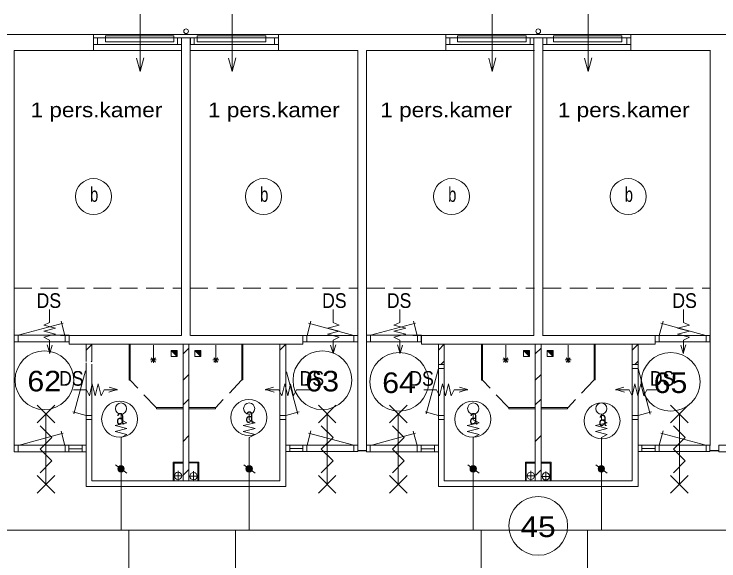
# Model space of a CAD drawing. Extents: x 295824 to 414724, y 24924 to 109024.
# Drawn here: x 308090 to 320090, y 38568 to 47876 of the extents above; entities that cross this region are included whole.
import ezdxf
from ezdxf.enums import TextEntityAlignment as Align

# ---------------------------------------------------------------- set-up
doc = ezdxf.new("R2010")
doc.units = 0
doc.header["$LTSCALE"] = 100
doc.linetypes.add('DOT_DASHED', pattern=[7.7, 5, -1.2, 0.3, -1.2])
doc.linetypes.add('MEDIUM_DASHED', pattern=[4.5, 3, -1.5])
for name, color, linetype, lineweight in [('1', 7, 'Continuous', 13), ('16', 7, 'Continuous', 13), ('24', 7, 'Continuous', 13), ('61', 7, 'Continuous', 13)]:
    doc.layers.add(name, color=color, linetype=linetype, lineweight=lineweight)

msp = doc.modelspace()

# ---------------------------------------------------------------- hatches: boundary and pattern name
at = {"layer": '24'}
for points in [[(309964.5, 40135, 1), (309855.9, 40135, 1)], [(312146.5, 40135, 1), (312037.9, 40135, 1)], [(315960.8, 40135, 1), (315852.2, 40135, 1)], [(318142.8, 40135, 1), (318034.2, 40135, 1)]]:
    msp.add_hatch(color=256, dxfattribs=at).paths.add_polyline_path(points)
at = {"layer": '61'}
for points in [[(310864.9, 42048.6), (310764.9, 42148.6), (310864.9, 42148.6)], [(311267.9, 42048.6), (311167.9, 42148.6), (311267.9, 42148.6)], [(316862.8, 42048.6), (316762.8, 42148.6), (316862.8, 42148.6)], [(317265.8, 42048.6), (317165.8, 42148.6), (317265.8, 42148.6)]]:
    msp.add_hatch(color=256, dxfattribs=at).paths.add_polyline_path(points)

# ---------------------------------------------------------------- linework, layer by layer
at = {"layer": '1'}
for p, q in [((309910.2, 40103.6), (309910.2, 39093.2)), ((312092.2, 40097), (312092.2, 39093.2)), ((315906.5, 40103.6), (315906.5, 39093.2)), ((318088.5, 40097), (318088.5, 39093.2)), ((310043.5, 38210.2), (310043.5, 39093.2)), ((311859, 38205.2), (311859, 39093.2)), ((316039.8, 38210.2), (316039.8, 39093.2)), ((317855.3, 38205.2), (317855.3, 39093.2))]:
    msp.add_line(p, q, dxfattribs=at)
at = {"layer": '16'}
for p, q in [((308594.4, 42478.5), (308794.4, 42528.5)), ((313624.7, 42478.5), (313424.7, 42528.5)), ((314557.3, 42478.5), (314757.3, 42528.5)), ((319587.6, 42478.5), (319387.6, 42528.5)), ((309470.8, 41380.3), (309420.8, 41580.3)), ((312748.2, 41380.3), (312798.2, 41580.3)), ((315433.7, 41380.3), (315383.7, 41580.3)), ((318711.2, 41380.3), (318761.2, 41580.3))]:
    msp.add_line(p, q, dxfattribs=at)
at = {"layer": '24'}
for p, q in [((310235, 46901.4), (310175.4, 47123.8)), ((311800.7, 46901.4), (311741.1, 47123.8)), ((316231.3, 46901.4), (316171.7, 47123.8)), ((317863.6, 46901.4), (317804, 47123.8)), ((308697.7, 42103.1), (308652.7, 42247.3)), ((313521.3, 42103.1), (313566.3, 42247.3)), ((314660.7, 42103.1), (314615.7, 42247.3)), ((319484.2, 42103.1), (319529.2, 42247.3)), ((308740.2, 42238.9), (308697.7, 42103.1)), ((313478.9, 42238.9), (313521.3, 42103.1)), ((314703.1, 42238.9), (314660.7, 42103.1)), ((319441.8, 42238.9), (319484.2, 42103.1)), ((309710.4, 41526.2), (309846.2, 41483.7)), ((312508.6, 41526.2), (312372.8, 41483.7)), ((315673.3, 41526.2), (315809.1, 41483.7)), ((318471.6, 41526.2), (318335.8, 41483.7)), ((309846.2, 41483.7), (309702, 41438.7)), ((312372.8, 41483.7), (312517, 41438.7)), ((315809.1, 41483.7), (315665, 41438.7)), ((318335.8, 41483.7), (318480, 41438.7)), ((309910.2, 40620.3), (309910.2, 40080.9)), ((312092.2, 40620.3), (312092.2, 40112)), ((315906.5, 40620.3), (315906.5, 40080.9)), ((318088.5, 40620.3), (318088.5, 40112)), ((309818.6, 40205.8), (310010.2, 40064.1)), ((312000.6, 40205.8), (312192.1, 40064.1)), ((315814.9, 40205.8), (316006.4, 40064.1)), ((317996.9, 40205.8), (318188.4, 40064.1)), ((304097.2, 39093.2), (328693.9, 39093.2))]:
    msp.add_line(p, q, dxfattribs=at)
for points in [[(310235, 47876.3), (310235, 46901.4), (310296.7, 47131.6)], [(311800.7, 47876.3), (311800.7, 46901.4), (311862.4, 47131.6)], [(316231.3, 47876.3), (316231.3, 46901.4), (316293, 47131.6)], [(317863.6, 47876.3), (317863.6, 46901.4), (317925.3, 47131.6)], [(308794.4, 42528.5), (308594.4, 42578.5), (308694.4, 42628.5), (308694.4, 42847.3)], [(313424.7, 42528.5), (313624.7, 42578.5), (313524.7, 42628.5), (313524.7, 42847.3)], [(314757.3, 42528.5), (314557.3, 42578.5), (314657.3, 42628.5), (314657.3, 42847.3)], [(319387.6, 42528.5), (319587.6, 42578.5), (319487.6, 42628.5), (319487.6, 42847.3)], [(308694.4, 42097.3), (308694.4, 42328.5), (308594.4, 42378.5), (308794.4, 42428.5), (308594.4, 42478.5)], [(313524.7, 42097.3), (313524.7, 42328.5), (313624.7, 42378.5), (313424.7, 42428.5), (313624.7, 42478.5)], [(314657.3, 42097.3), (314657.3, 42328.5), (314557.3, 42378.5), (314757.3, 42428.5), (314557.3, 42478.5)], [(319487.6, 42097.3), (319487.6, 42328.5), (319587.6, 42378.5), (319387.6, 42428.5), (319587.6, 42478.5)], [(309420.8, 41580.3), (309370.8, 41380.3), (309320.8, 41480.3), (309102, 41480.3)], [(309852, 41480.3), (309620.8, 41480.3), (309570.8, 41380.3), (309520.8, 41580.3), (309470.8, 41380.3)], [(312367, 41480.3), (312598.2, 41480.3), (312648.2, 41380.3), (312698.2, 41580.3), (312748.2, 41380.3)], [(312798.2, 41580.3), (312848.2, 41380.3), (312898.2, 41480.3), (313117, 41480.3)], [(315383.7, 41580.3), (315333.7, 41380.3), (315283.7, 41480.3), (315065, 41480.3)], [(315815, 41480.3), (315583.7, 41480.3), (315533.7, 41380.3), (315483.7, 41580.3), (315433.7, 41380.3)], [(318330, 41480.3), (318561.2, 41480.3), (318611.2, 41380.3), (318661.2, 41580.3), (318711.2, 41380.3)], [(318761.2, 41580.3), (318811.2, 41380.3), (318861.2, 41480.3), (319079.9, 41480.3)], [(309910.2, 41070.3), (309910.2, 40970.3), (310010.2, 40920.3), (309810.2, 40870.3), (310010.2, 40820.3), (309810.2, 40770.3), (310010.2, 40720.3), (309910.2, 40670.3), (309910.2, 40620.3)], [(312092.2, 41070.3), (312092.2, 40970.3), (312192.2, 40920.3), (311992.2, 40870.3), (312192.2, 40820.3), (311992.2, 40770.3), (312192.2, 40720.3), (312092.2, 40670.3), (312092.2, 40620.3)], [(315906.5, 41070.3), (315906.5, 40970.3), (316006.5, 40920.3), (315806.5, 40870.3), (316006.5, 40820.3), (315806.5, 40770.3), (316006.5, 40720.3), (315906.5, 40670.3), (315906.5, 40620.3)], [(318088.5, 41070.3), (318088.5, 40970.3), (318188.5, 40920.3), (317988.5, 40870.3), (318188.5, 40820.3), (317988.5, 40770.3), (318188.5, 40720.3), (318088.5, 40670.3), (318088.5, 40620.3)]]:
    msp.add_lwpolyline(points, dxfattribs=at)
for points in [[(309643.7, 47405.5), (310809.7, 47405.5), (310809.7, 47505.5), (309643.7, 47505.5)], [(311209.4, 47405.5), (312375.4, 47405.5), (312375.4, 47505.5), (311209.4, 47505.5)], [(315640, 47405.5), (316805.9, 47405.5), (316805.9, 47505.5), (315640, 47505.5)], [(317272.3, 47405.5), (318438.2, 47405.5), (318438.2, 47505.5), (317272.3, 47505.5)]]:
    msp.add_lwpolyline(points, close=True, dxfattribs=at)
for centre, radius in [((309910.2, 41162), 95), ((312092.2, 41162), 95), ((315906.5, 41162), 95), ((318088.5, 41162), 95), ((309910.2, 40135), 54.3), ((312092.2, 40135), 54.3), ((315906.5, 40135), 54.3), ((318088.5, 40135), 54.3)]:
    msp.add_circle(centre, radius, dxfattribs=at)
at = {"layer": '61'}
for p, q in [((301828.9, 47527.9), (333452, 47527.9)), ((309440.9, 47257.3), (309440.9, 47527.3)), ((312589.9, 47257.3), (312589.9, 47527.3)), ((313820.3, 47527.9), (333174.1, 47527.9)), ((315441, 47257.3), (315441, 47527.3)), ((318589.9, 47257.3), (318589.9, 47527.3)), ((309441.7, 47472.1), (310940.7, 47472.1)), ((309441.7, 47358.1), (309441.7, 47472.1)), ((309508.7, 47358.1), (309508.7, 47471.5)), ((310873.7, 47472.1), (312589.7, 47472.1)), ((310873.7, 47358.5), (310873.7, 47472.1)), ((310940.7, 47359.1), (310940.7, 47472.1)), ((310940.9, 47257.3), (310940.9, 47472.1)), ((311089.9, 47257.3), (311089.9, 47472.1)), ((311090.7, 47358.1), (311090.7, 47472.1)), ((311157.7, 47358.1), (311157.7, 47471.5)), ((312522.7, 47358.5), (312522.7, 47471.5)), ((312589.7, 47359.1), (312589.7, 47472.1)), ((315441.8, 47472.1), (316940.8, 47472.1)), ((315441.8, 47358.1), (315441.8, 47472.1)), ((315508.8, 47358.1), (315508.8, 47471.5)), ((316873.8, 47472.1), (318589.8, 47472.1)), ((316873.8, 47358.5), (316873.8, 47472.1)), ((316940.8, 47359.1), (316940.8, 47472.1)), ((316941, 47257.3), (316941, 47472.1)), ((317089.9, 47257.3), (317089.9, 47472.1)), ((317090.8, 47358.1), (317090.8, 47472.1)), ((317157.8, 47358.1), (317157.8, 47471.5)), ((318522.8, 47358.5), (318522.8, 47471.5)), ((318589.8, 47359.1), (318589.8, 47472.1)), ((309441.7, 47358.1), (310939.8, 47358.1)), ((311090.7, 47358.1), (312588.8, 47358.1)), ((315441.8, 47358.1), (316939.9, 47358.1)), ((317090.8, 47358.1), (318588.8, 47358.1)), ((308090.1, 40536.9), (308090.1, 47257.9)), ((313940.1, 40532.9), (313940.1, 47257.9)), ((314090.1, 40532.9), (314090.1, 47257.9)), ((314098.9, 47257.9), (316948.9, 47257.9)), ((319948.9, 47257.9), (317098.9, 47257.9)), ((319940.1, 40532.9), (319940.1, 47257.9)), ((308160.8, 42409.2), (308928.1, 42614.8)), ((308955.3, 42407.1), (308890.3, 42649.8)), ((313077.1, 42405.1), (313142.2, 42647.8)), ((313871.7, 42407.2), (313104.4, 42612.8)), ((314158.7, 42409.2), (314926, 42614.8)), ((314953.3, 42407.1), (314888.2, 42649.8)), ((319075.1, 42405.1), (319140.1, 42647.8)), ((319869.6, 42407.2), (319102.3, 42612.8)), ((308158.2, 42299.1), (308158.2, 42409.1)), ((310940.8, 42407.9), (308880.8, 42407.9)), ((308958.2, 42299.1), (308958.2, 42409.1)), ((309025.2, 42299.1), (309025.2, 42409.1)), ((311090.8, 42407.9), (313940.1, 42407.9)), ((311090.8, 42407.9), (313033.3, 42407.9)), ((313007.3, 42297.1), (313007.3, 42407.1)), ((313074.3, 42297.1), (313074.3, 42407.1)), ((313874.3, 42297.1), (313874.3, 42407.1)), ((313940.2, 42297.4), (313940.2, 42407.8)), ((314156.1, 42299.1), (314156.1, 42409.1)), ((316938.8, 42407.9), (314878.8, 42407.9)), ((314956.1, 42299.1), (314956.1, 42409.1)), ((315023.1, 42299.1), (315023.1, 42409.1)), ((317088.7, 42407.9), (319031.2, 42407.9)), ((317088.8, 42407.9), (319938, 42407.9)), ((319005.2, 42297.1), (319005.2, 42407.1)), ((319072.2, 42297.1), (319072.2, 42407.1)), ((319872.2, 42297.1), (319872.2, 42407.1)), ((319938.1, 42297.4), (319938.1, 42407.8)), ((309023.1, 42299.4), (308092.3, 42299.4)), ((309026.1, 42257.9), (312616.2, 42257.9)), ((309315.9, 41961), (309315.9, 42257.9)), ((309315.9, 42157.2), (309416.3, 42257.6)), ((309414.6, 41963.8), (309414.6, 42257.9)), ((310048.5, 41644.6), (310048.5, 42253)), ((310066.5, 41644.6), (310066.5, 42253)), ((310965.8, 42257.9), (310965.8, 41262.7)), ((311065.8, 42257.9), (311065.8, 41409)), ((311966.4, 41650.7), (311966.4, 42255.5)), ((311984.4, 41650.7), (311984.4, 42255.5)), ((312616.2, 41984), (312616.2, 42258.3)), ((312616.4, 42157.2), (312716.8, 42257.6)), ((312716, 41992.3), (312716, 42257.9)), ((313009.4, 42297.4), (313940.2, 42297.4)), ((315021, 42299.4), (314090.2, 42299.4)), ((315024, 42257.9), (318614.2, 42257.9)), ((315313.8, 41911.5), (315313.8, 42257.9)), ((315313.8, 42157.2), (315414.2, 42257.6)), ((315412.5, 41911.5), (315412.5, 42257.9)), ((316046.5, 41644.6), (316046.5, 42253)), ((316064.5, 41644.6), (316064.5, 42253)), ((316963.7, 42257.9), (316963.7, 39932.9)), ((317063.7, 42257.9), (317063.7, 39932.9)), ((317964.3, 41650.7), (317964.3, 42255.5)), ((317982.3, 41650.7), (317982.3, 42255.5)), ((318614.2, 41911.9), (318614.2, 42258.3)), ((318614.3, 42157.2), (318714.7, 42257.6)), ((318713.9, 41911.5), (318713.9, 42257.9)), ((319007.3, 42297.4), (319938.1, 42297.4)), ((310461.4, 42039.2), (310461.4, 42239.2)), ((310966.3, 42093), (311064.8, 42191.5)), ((311525.9, 42039.2), (311525.9, 42239.2)), ((316459.4, 42039.2), (316459.4, 42239.2)), ((316964.2, 42093), (317062.7, 42191.5)), ((317523.8, 42039.2), (317523.8, 42239.2)), ((310496.8, 42024.5), (310426.1, 41953.8)), ((310496.8, 41953.8), (310426.1, 42024.5)), ((310461.4, 42039.2), (310461.4, 41939.2)), ((311561.3, 42024.5), (311490.5, 41953.8)), ((311561.3, 41953.8), (311490.5, 42024.5)), ((311525.9, 42039.2), (311525.9, 41939.2)), ((312615.8, 42005.8), (312615.8, 40977.5)), ((312715.9, 41578.4), (312715.9, 42016.7)), ((316494.7, 42024.5), (316424, 41953.8)), ((316494.7, 41953.8), (316424, 42024.5)), ((316459.4, 42039.2), (316459.4, 41939.2)), ((317559.2, 42024.5), (317488.5, 41953.8)), ((317559.2, 41953.8), (317488.5, 42024.5)), ((317523.8, 42039.2), (317523.8, 41939.2)), ((309315.7, 40977.9), (309315.7, 41940.6)), ((309400.3, 41955.2), (309414.9, 41969.9)), ((309415.7, 41918.8), (309415.7, 40977.9)), ((310511.4, 41989.2), (310411.4, 41989.2)), ((311575.9, 41989.2), (311475.9, 41989.2)), ((315313.6, 40977.9), (315313.6, 41911.9)), ((315413.6, 41911.9), (315313.6, 41911.9)), ((315356.2, 41913.2), (315412.8, 41969.9)), ((315413.6, 41911.9), (315413.6, 40977.9)), ((316509.4, 41989.2), (316409.4, 41989.2)), ((317573.8, 41989.2), (317473.8, 41989.2)), ((318613.7, 41911.5), (318613.7, 40977.5)), ((318614.2, 41911.5), (318714.3, 41911.5)), ((318658.1, 41913.2), (318714.7, 41969.9)), ((318713.7, 40976.7), (318713.7, 41911.5)), ((309305.8, 41803.7), (309109, 41069.1)), ((312729.4, 41789.3), (312922.4, 41068.7)), ((315313.8, 41841.3), (315106.9, 41069.1)), ((315413.7, 41844.9), (315313.6, 41844.9)), ((318613.6, 41844.5), (318713.7, 41844.5)), ((318713.4, 41841), (318920.4, 41068.7)), ((310048.5, 41644.6), (310066.5, 41644.6)), ((310966.3, 41645.4), (311064.8, 41743.9)), ((311065.8, 41641.3), (311065.8, 39932.9)), ((311966.4, 41650.7), (311984.4, 41650.7)), ((316046.5, 41644.6), (316064.5, 41644.6)), ((316964.2, 41645.4), (317062.7, 41743.9)), ((317964.3, 41650.7), (317982.3, 41650.7)), ((310965.8, 41630.2), (310965.8, 39932.9)), ((312715.8, 40976.7), (312715.8, 41624.6)), ((318713.8, 41578.4), (318713.8, 41468)), ((310966.3, 41222.9), (311064.8, 41321.4)), ((316964.2, 41222.9), (317062.7, 41321.4)), ((308482.7, 40919.8), (308782.7, 41219.8)), ((308782.7, 40919.8), (308482.7, 41219.8)), ((311516.8, 41176.7), (311066.8, 41176.7)), ((311516.8, 41176.7), (311516.8, 41158.7)), ((313270.4, 40919.8), (313570.4, 41219.8)), ((313570.4, 40919.8), (313270.4, 41219.8)), ((314480.6, 40919.8), (314780.6, 41219.8)), ((314780.6, 40919.8), (314480.6, 41219.8)), ((317514.8, 41176.7), (317064.7, 41176.7)), ((317514.8, 41176.7), (317514.8, 41158.7)), ((319268.3, 40919.8), (319568.3, 41219.8)), ((319568.3, 40919.8), (319268.3, 41219.8)), ((308632.7, 41069.8), (308632.7, 39869.8)), ((309315.9, 41043.9), (309088.6, 41104.8)), ((309415.5, 41044.9), (309316.2, 41044.9)), ((310965.4, 41158.7), (310515.1, 41158.7)), ((311516.8, 41158.7), (311066.8, 41158.7)), ((312615.9, 41044.5), (312715.2, 41044.5)), ((312715.5, 41043.5), (312942.8, 41104.4)), ((313420.4, 41069.8), (313420.4, 39869.8)), ((314630.6, 41069.8), (314630.6, 39869.8)), ((315313.8, 41043.9), (315086.5, 41104.8)), ((315413.5, 41044.9), (315314.1, 41044.9)), ((316963.4, 41158.7), (316513, 41158.7)), ((317514.8, 41158.7), (317064.7, 41158.7)), ((318613.8, 41044.5), (318713.2, 41044.5)), ((318713.4, 41043.5), (318940.8, 41104.4)), ((319418.3, 41069.8), (319418.3, 39869.8)), ((309415.7, 40977.9), (309315.7, 40977.9)), ((309315.8, 40975.3), (309315.8, 40188.2)), ((309415.8, 40638.2), (309415.8, 40975.3)), ((312615.8, 40977.5), (312715.8, 40977.5)), ((312715.8, 40977.5), (312715.8, 40532.9)), ((315413.6, 40977.9), (315313.6, 40977.9)), ((315313.7, 40975.3), (315313.7, 40188.2)), ((315413.7, 40638.2), (315413.7, 40975.3)), ((318613.7, 40977.5), (318613.7, 39932.9)), ((318613.7, 40977.5), (318713.7, 40977.5)), ((318713.7, 40977.5), (318713.7, 40532.9)), ((308159.5, 40535.1), (308926.8, 40740.7)), ((308954.1, 40532.9), (308889.1, 40775.7)), ((310966.3, 40603), (311064.8, 40701.4)), ((313077.1, 40536.8), (313142.2, 40779.5)), ((313871.7, 40539), (313104.4, 40744.6)), ((314157.5, 40535.1), (314924.8, 40740.7)), ((314952, 40532.9), (314887, 40775.7)), ((316964.2, 40603), (317062.7, 40701.4)), ((319075.1, 40536.8), (319140.1, 40779.5)), ((319869.6, 40539), (319102.3, 40744.6)), ((308157, 40424.9), (308157, 40534.9)), ((308957, 40424.9), (308957, 40534.9)), ((309024, 40424.9), (309024, 40534.9)), ((309024.8, 40475.7), (309249.5, 40475.7)), ((309249.5, 40424.9), (309249.5, 40534.9)), ((312781.8, 40428.8), (312781.8, 40538.8)), ((313006.5, 40479.6), (312781.8, 40479.6)), ((313007.3, 40428.8), (313007.3, 40538.8)), ((313074.3, 40428.8), (313074.3, 40538.8)), ((313874.3, 40428.8), (313874.3, 40538.8)), ((313940.2, 40447.3), (314090.2, 40447.3)), ((313940.2, 40443.5), (314090.2, 40443.5)), ((313942.3, 40447.3), (314092.3, 40447.3)), ((313942.3, 40443.5), (314092.3, 40443.5)), ((314154.9, 40424.9), (314154.9, 40534.9)), ((314954.9, 40424.9), (314954.9, 40534.9)), ((315021.9, 40424.9), (315021.9, 40534.9)), ((315022.7, 40475.7), (315247.4, 40475.7)), ((315247.4, 40424.9), (315247.4, 40534.9)), ((318779.7, 40428.8), (318779.7, 40538.8)), ((319004.4, 40479.6), (318779.7, 40479.6)), ((319005.2, 40428.8), (319005.2, 40538.8)), ((319072.2, 40428.8), (319072.2, 40538.8)), ((319872.2, 40428.8), (319872.2, 40538.8)), ((319939.7, 40447.3), (320089.7, 40447.3)), ((319939.7, 40443.5), (320089.7, 40443.5)), ((309315.8, 40432.9), (309315.8, 39832.9)), ((312715.8, 39832.9), (312715.8, 40432.9)), ((310797.5, 40248.9), (310965.3, 40248.9)), ((310797.5, 40248.9), (310797.5, 39935.2)), ((310812.5, 40233.9), (310966.5, 40233.9)), ((310812.5, 40233.9), (310812.5, 39934.9)), ((311066.5, 40250.3), (311235.6, 40250.3)), ((311220.7, 40235.1), (311067.3, 40235.1)), ((311220.7, 39933.5), (311220.7, 40235.1)), ((311235.6, 39932.9), (311235.6, 40250.3)), ((316795.9, 40248), (316963.6, 40248)), ((316795.9, 40248), (316795.9, 39932.9)), ((316810.2, 40234.4), (316963.6, 40234.4)), ((316810.2, 40234.4), (316810.2, 39934)), ((317063.7, 40234.4), (317218.4, 40234.4)), ((317064.7, 40248), (317233.4, 40248)), ((317218.4, 39932.9), (317218.4, 40234.4)), ((317233.4, 39932.9), (317233.4, 40248)), ((310967.7, 40024.9), (311065, 40122.2)), ((316971.7, 40026.8), (317057, 40112.1)), ((308482.7, 39719.8), (308782.7, 40019.8)), ((308782.7, 39719.8), (308482.7, 40019.8)), ((313270.4, 39719.8), (313570.4, 40019.8)), ((313570.4, 39719.8), (313270.4, 40019.8)), ((314480.6, 39719.8), (314780.6, 40019.8)), ((314780.6, 39719.8), (314480.6, 40019.8)), ((319268.3, 39719.8), (319568.3, 40019.8)), ((319568.3, 39719.8), (319268.3, 40019.8)), ((311090.6, 39932.9), (311279.7, 39932.9)), ((311104.2, 39932.9), (312615.8, 39932.9)), ((309315.8, 39832.9), (311290.8, 39832.9)), ((311049.9, 39832.9), (312715.8, 39832.9))]:
    msp.add_line(p, q, dxfattribs=at)
at = {"layer": '61', "linetype": 'MEDIUM_DASHED'}
for p, q in [((308090.1, 43208.1), (310940.1, 43208.1)), ((311090.1, 43208.1), (313940.1, 43208.1)), ((314101.9, 43208.1), (316951.9, 43208.1)), ((317102.6, 43208.1), (319932.3, 43208.1)), ((310507.7, 41179.8), (310065.9, 41644.8)), ((311962, 41643.1), (311518, 41175.8)), ((316505.7, 41179.8), (316063.8, 41644.8)), ((317959.9, 41643.1), (317515.9, 41175.8))]:
    msp.add_line(p, q, dxfattribs=at)
at = {"layer": '61', "linetype": 'DOT_DASHED'}
for p, q in [((310881.4, 39934.8), (310881.4, 40098.9)), ((311145.3, 39934.3), (311145.3, 40093.7)), ((316888.9, 39934.8), (316888.9, 40098.9)), ((317141.8, 39933.5), (317141.8, 40092.8)), ((310970.6, 40016), (310806.6, 40016)), ((311230.4, 40008.6), (311066.3, 40008.6)), ((311230.5, 40008.6), (311066.5, 40008.6)), ((316967.7, 40015.2), (316815.1, 40015.2)), ((316963, 40015.2), (316826, 40015.2)), ((317227.5, 40007.7), (317063.4, 40007.7)), ((317213.7, 40007.7), (317085.8, 40007.7))]:
    msp.add_line(p, q, dxfattribs=at)
at = {"layer": '61'}
for points in [[(308090.1, 47257.9), (310940.1, 47257.9), (310940.1, 42407.9)], [(308090.2, 47257.9), (310940.2, 47257.9), (310940.2, 42407.9)], [(313940.1, 47257.9), (311090.1, 47257.9), (311090.1, 42407.9)], [(313940.2, 47257.9), (311090.2, 47257.9), (311090.2, 42407.9)], [(314090.2, 47257.9), (316940.2, 47257.9), (316940.2, 42407.9)], [(314090.3, 47257.9), (316940.3, 47257.9), (316940.3, 42407.9)], [(319940.2, 47257.9), (317090.2, 47257.9), (317090.2, 42407.9)], [(319940.3, 47257.9), (317090.3, 47257.9), (317090.3, 42407.9)], [(308092.3, 42299.4), (308092.3, 42409.8), (309025.6, 42409.8)], [(310940.8, 42407.9), (309026.1, 42407.9), (309026.1, 42257.9)], [(313006.9, 42407.8), (313006.9, 42257.9), (312601.5, 42257.9)], [(314090.2, 42299.4), (314090.2, 42409.8), (315023.5, 42409.8)], [(316938.7, 42407.9), (315024, 42407.9), (315024, 42257.9)], [(319004.8, 42407.8), (319004.8, 42257.9), (318599.4, 42257.9)], [(310764.9, 42148.6), (310864.9, 42148.6), (310864.9, 42048.6)], [(311167.9, 42148.6), (311267.9, 42148.6), (311267.9, 42048.6)], [(316762.8, 42148.6), (316862.8, 42148.6), (316862.8, 42048.6)], [(317165.8, 42148.6), (317265.8, 42148.6), (317265.8, 42048.6)], [(310965.4, 41176.7), (310515.1, 41176.7), (310515.1, 41158.7)], [(316963.4, 41176.7), (316513, 41176.7), (316513, 41158.7)], [(309415.8, 41158.7), (309415.8, 39932.9), (311295.8, 39932.9)], [(315413.7, 41158.7), (315413.7, 39932.9), (317293.7, 39932.9)], [(312615.8, 40977.5), (312615.8, 39932.9), (312615.8, 40882.9)], [(308532.7, 40869.8), (308732.7, 40669.8), (308532.7, 40469.8), (308732.7, 40269.8), (308532.7, 40069.8)], [(313320.4, 40869.8), (313520.4, 40669.8), (313320.4, 40469.8), (313520.4, 40269.8), (313320.4, 40069.8)], [(314530.6, 40869.8), (314730.6, 40669.8), (314530.6, 40469.8), (314730.6, 40269.8), (314530.6, 40069.8)], [(317088.5, 39932.9), (318613.7, 39932.9), (318613.7, 40882.9)], [(319318.3, 40869.8), (319518.3, 40669.8), (319318.3, 40469.8), (319518.3, 40269.8), (319318.3, 40069.8)], [(315313.7, 40432.9), (315313.7, 39832.9), (318713.7, 39832.9), (318713.7, 40432.9)]]:
    msp.add_lwpolyline(points, dxfattribs=at)
for points in [[(310764.9, 42148.6), (310764.9, 42048.6), (310864.9, 42048.6)], [(310864.9, 42048.6), (310764.9, 42148.6), (310864.9, 42148.6)], [(311167.9, 42148.6), (311167.9, 42048.6), (311267.9, 42048.6)], [(311267.9, 42048.6), (311167.9, 42148.6), (311267.9, 42148.6)], [(316762.8, 42148.6), (316762.8, 42048.6), (316862.8, 42048.6)], [(316862.8, 42048.6), (316762.8, 42148.6), (316862.8, 42148.6)], [(317165.8, 42148.6), (317165.8, 42048.6), (317265.8, 42048.6)], [(317265.8, 42048.6), (317165.8, 42148.6), (317265.8, 42148.6)], [(308091, 40425.3), (308091, 40535.6), (309315.4, 40535.6), (309315.4, 40425.3)], [(313940.2, 40429.1), (313940.2, 40539.5), (312715.9, 40539.5), (312715.9, 40429.1)], [(314089, 40425.3), (314089, 40535.6), (315313.3, 40535.6), (315313.3, 40425.3)], [(319938.1, 40429.1), (319938.1, 40539.5), (318713.8, 40539.5), (318713.8, 40429.1)], [(320089.2, 40425.3), (320089.2, 40535.6), (321313.5, 40535.6), (321313.5, 40425.3)]]:
    msp.add_lwpolyline(points, close=True, dxfattribs=at)
for centre, radius in [((311017.9, 47584.2), 40), ((317012.8, 47584.2), 40), ((309441.3, 44769.7), 306.3), ((312336.8, 44769.7), 306.3), ((315538.5, 44769.7), 306.3), ((318545.3, 44769.7), 306.3), ((308605.9, 41643.7), 500), ((313338.8, 41643.7), 500), ((314647.4, 41615.9), 500), ((319269, 41615.9), 500), ((309886.8, 40980.6), 306.3), ((312086.2, 41008.4), 306.3), ((315900.4, 40980.6), 306.3), ((318099.9, 40952.7), 306.3), ((310881.4, 40015.2), 62.5), ((311145.9, 40009.3), 62.5), ((316887.7, 40015.2), 62.5), ((317141.8, 40008.4), 62.5), ((317013.9, 39164.1), 500)]:
    msp.add_circle(centre, radius, dxfattribs=at)

# ---------------------------------------------------------------- texts
at = {"layer": '24', "width": 0.9}
for p in [(308472.5, 42874.3), (313333.1, 42874.3), (314435.5, 42874.3), (319296.1, 42874.3), (308855.6, 41549.3), (312950, 41549.3), (314818.6, 41549.3), (318913, 41549.3)]:
    msp.add_text('DS', height=250, dxfattribs=at).set_placement(p)
at = {"layer": '61'}
for s, width, p in [('1 pers.kamer', 1.15, (308369.2, 46120.2)), ('1 pers.kamer', 1.15, (311391.4, 46120.2)), ('1 pers.kamer', 1.15, (314324.7, 46120.2)), ('1 pers.kamer', 1.15, (317346.9, 46120.2)), ('b', 0.75, (309383.3, 44680.6)), ('b', 0.75, (312278.8, 44680.6)), ('b', 0.75, (315480.5, 44680.6)), ('b', 0.75, (318487.3, 44680.6)), ('a', 0.75, (309828.8, 40891.4)), ('a', 0.75, (312028.2, 40919.2)), ('a', 0.75, (315842.4, 40891.4)), ('a', 0.75, (318041.9, 40863.5))]:
    msp.add_text(s, height=250, dxfattribs=dict(at, width=width)).set_placement(p)
for s, width, p in [('62', 1.1, (308602.9, 41453.9)), ('63', 1.1, (313335.9, 41453.9)), ('64', 1.1, (314644.4, 41426)), ('65', 1.1, (319266.1, 41426)), ('45', 1.15, (317011, 38974.2))]:
    msp.add_text(s, height=350, dxfattribs=dict(at, width=width)).set_placement(p, align=Align.CENTER)

doc.saveas('drawing.dxf')
